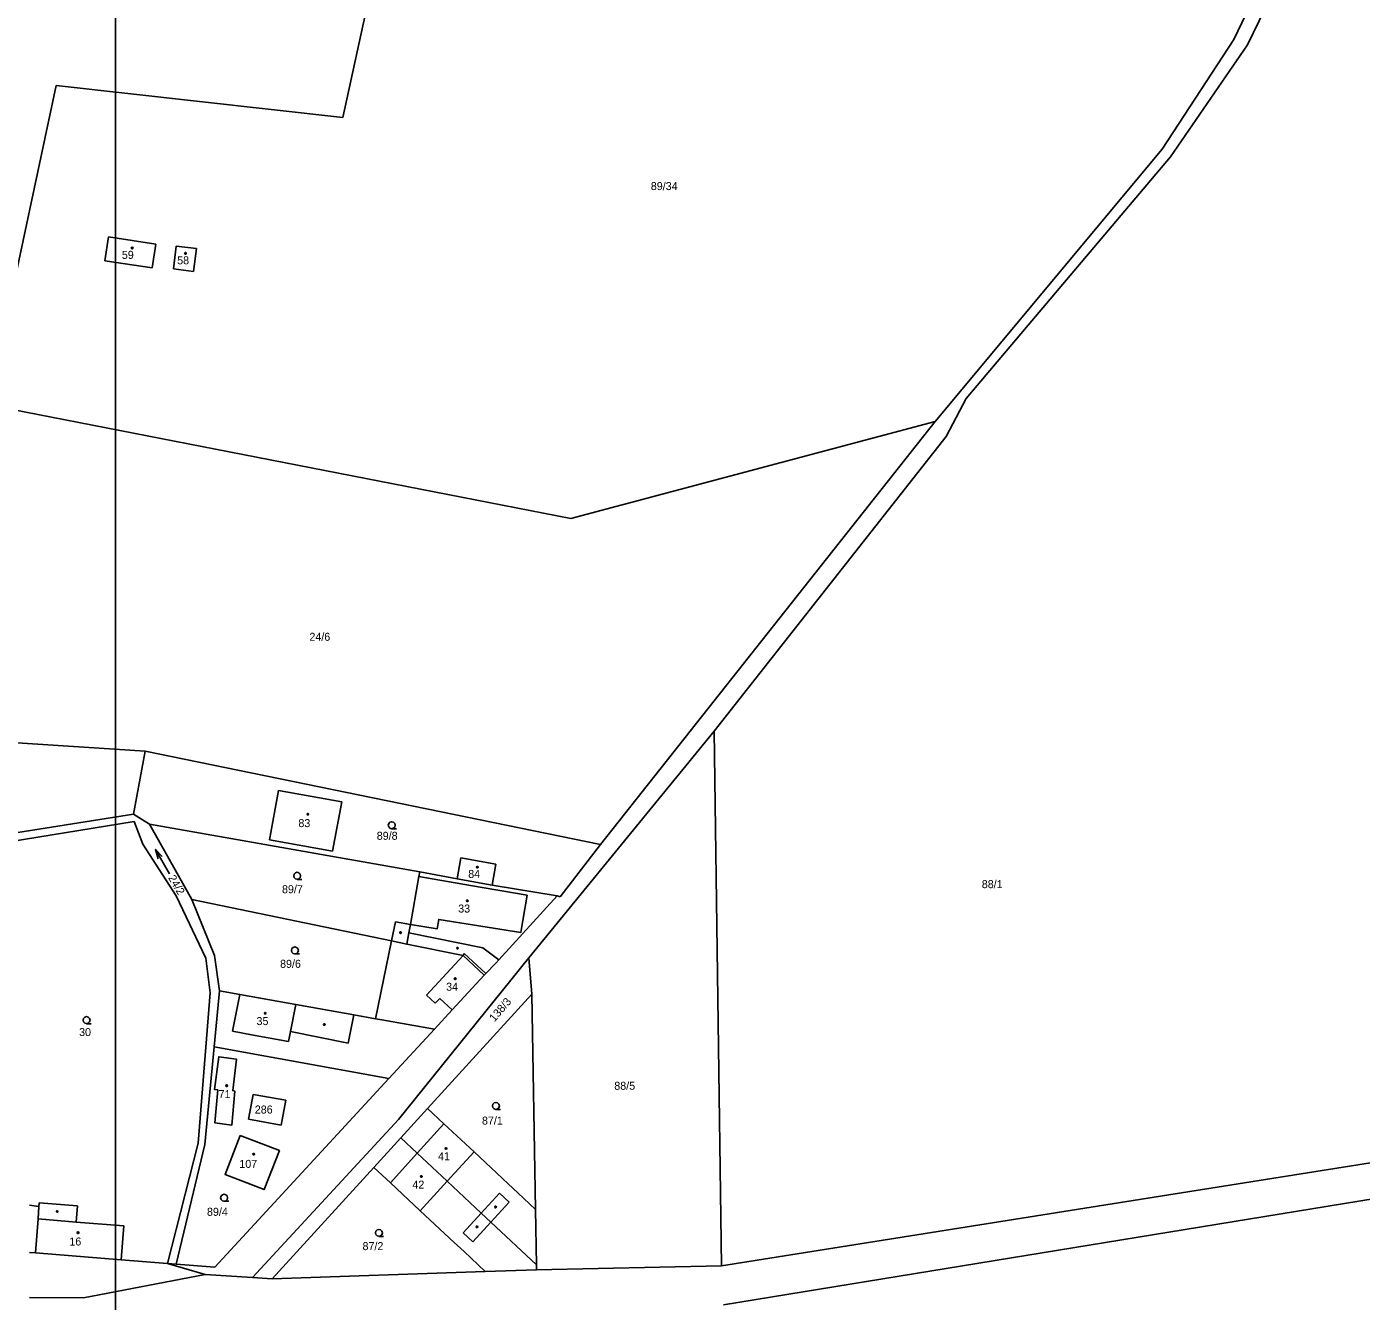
# Model space of a CAD drawing. Extents: x -752343 to -750336, y -1035826 to -1033329.
# Drawn here: x -751372.1 to -751088.6, y -1034441.1 to -1034170.4 of the extents above; entities that cross this region are included whole.
import ezdxf

# ---------------------------------------------------------------- set-up
doc = ezdxf.new("R2010")
doc.units = 0
for name, color, linetype in [('Default', 7, 'Continuous'), ('KN_HRANICE', 7, 'Continuous'), ('KN_KULTURY', 7, 'Continuous'), ('KN_PARCELY', 7, 'Continuous'), ('KN_SLUCKY', 7, 'Continuous'), ('LEGENDA', 7, 'Continuous')]:
    doc.layers.add(name, color=color, linetype=linetype)

# ---------------------------------------------------------------- blocks, each defined once
blk = doc.blocks.new('304')
at = {"layer": 'Default'}
blk.add_lwpolyline([(0, 0), (-0.38, 0.1), (-0.65, 0.37), (-0.75, 0.74), (-0.65, 1.11), (-0.38, 1.38), (-0.01, 1.48), (0.36, 1.38), (0.63, 1.11), (0.73, 0.73), (0.63, 0.35), (0.36, 0.08), (-0.02, -0.02), (0.98, -0.02)], dxfattribs=at)
blk = doc.blocks.new('NAHRADNI_SYMBOL')
at = {"layer": 'Default'}
blk.add_lwpolyline([(0.09, 0.15), (0.18, 0), (0.09, -0.15), (-0.09, -0.15), (-0.18, 0), (-0.09, 0.15), (0.09, 0.15)], dxfattribs=at)
blk = doc.blocks.new('802')
at = {"layer": 'Default'}
blk.add_line((-3, 0), (3, 0), dxfattribs=at)
blk.add_lwpolyline([(1, 0.5), (3, 0), (1, -0.5)], dxfattribs=at)
blk = doc.blocks.new('402')
at = {"layer": 'Default'}
blk.add_lwpolyline([(0.09, 0.15), (0.18, 0), (0.09, -0.15), (-0.09, -0.15), (-0.18, 0), (-0.09, 0.15), (0.09, 0.15)], dxfattribs=at)

msp = doc.modelspace()

# ---------------------------------------------------------------- linework, layer by layer
at = {"layer": 'KN_HRANICE'}
for p, q in [((-751291.67, -1034128.59), (-751304.92, -1034189.73)), ((-751115.71, -1034173.12), (-751109.66, -1034160.4)), ((-751112.8, -1034174.3), (-751106.52, -1034161.33)), ((-751130.94, -1034196.4), (-751115.71, -1034173.12)), ((-751129.14, -1034198.04), (-751112.8, -1034174.3)), ((-751365.81, -1034182.88), (-751380.27, -1034250.73)), ((-751304.92, -1034189.73), (-751365.81, -1034182.88)), ((-751179.17, -1034254.29), (-751130.94, -1034196.4)), ((-751172.58, -1034249.37), (-751129.14, -1034198.04)), ((-751354.68, -1034215.08), (-751355.44, -1034220.15)), ((-751344.64, -1034216.57), (-751354.68, -1034215.08)), ((-751345.39, -1034221.65), (-751344.64, -1034216.57)), ((-751340.3, -1034217), (-751340.9, -1034221.84)), ((-751336.02, -1034217.53), (-751340.3, -1034217)), ((-751336.62, -1034222.38), (-751336.02, -1034217.53)), ((-751355.44, -1034220.15), (-751345.39, -1034221.65)), ((-751340.9, -1034221.84), (-751336.62, -1034222.38)), ((-751176.82, -1034257.44), (-751172.58, -1034249.37)), ((-751256.5, -1034274.89), (-751380.27, -1034250.73)), ((-751179.17, -1034254.29), (-751256.5, -1034274.89)), ((-751250.21, -1034344.11), (-751179.17, -1034254.29)), ((-751176.82, -1034257.44), (-751226.06, -1034320.01)), ((-751226.06, -1034320.01), (-751265.43, -1034368.17)), ((-751226.06, -1034320.01), (-751224.54, -1034433.54)), ((-751401.38, -1034320.74), (-751346.88, -1034324.25)), ((-751346.88, -1034324.25), (-751349.38, -1034337.65)), ((-751250.21, -1034344.11), (-751346.88, -1034324.25)), ((-751318.58, -1034332.59), (-751320.52, -1034343.11)), ((-751305.12, -1034335.02), (-751318.58, -1034332.59)), ((-751307.12, -1034345.5), (-751305.12, -1034335.02)), ((-751388.63, -1034343.88), (-751349.38, -1034337.65)), ((-751349.22, -1034339.19), (-751386, -1034345.21)), ((-751349.38, -1034337.65), (-751345.97, -1034339.77)), ((-751347.37, -1034344.02), (-751349.22, -1034339.19)), ((-751345.97, -1034339.77), (-751336.97, -1034355.77)), ((-751345.97, -1034339.77), (-751288.59, -1034349.93)), ((-751320.52, -1034343.11), (-751307.12, -1034345.5)), ((-751340.29, -1034354.97), (-751347.37, -1034344.02)), ((-751258.79, -1034355.2), (-751250.21, -1034344.11)), ((-751280.62, -1034351.41), (-751279.88, -1034346.92)), ((-751279.88, -1034346.92), (-751272.41, -1034348.25)), ((-751272.41, -1034348.25), (-751273.19, -1034352.72)), ((-751290.57, -1034361.09), (-751288.76, -1034350.86)), ((-751288.76, -1034350.86), (-751288.59, -1034349.93)), ((-751288.59, -1034349.93), (-751280.62, -1034351.41)), ((-751273.19, -1034352.72), (-751280.62, -1034351.41)), ((-751273.19, -1034352.72), (-751259.44, -1034355.02)), ((-751340.29, -1034354.97), (-751334, -1034368.23)), ((-751294.56, -1034364.56), (-751336.97, -1034355.77)), ((-751332.18, -1034367.69), (-751336.97, -1034355.77)), ((-751271.8, -1034368.57), (-751259.44, -1034355.02)), ((-751259.44, -1034355.02), (-751258.79, -1034355.2)), ((-751294.56, -1034364.56), (-751293.72, -1034360.54)), ((-751293.72, -1034360.54), (-751290.57, -1034361.09)), ((-751298.02, -1034381.09), (-751294.56, -1034364.56)), ((-751291.3, -1034365.23), (-751294.56, -1034364.56)), ((-751279.4, -1034367.69), (-751291.3, -1034365.23)), ((-751334, -1034368.23), (-751333.12, -1034375.56)), ((-751331.09, -1034375.2), (-751332.18, -1034367.69)), ((-751265.43, -1034368.17), (-751293.13, -1034402.46)), ((-751279.4, -1034367.69), (-751274.9, -1034371.84)), ((-751272.46, -1034369.29), (-751271.8, -1034368.57)), ((-751264.81, -1034375.86), (-751265.43, -1034368.17)), ((-751274.9, -1034371.84), (-751274.57, -1034371.5)), ((-751274.57, -1034371.5), (-751272.46, -1034369.29)), ((-751274.9, -1034371.84), (-751281.69, -1034379.21)), ((-751333.12, -1034375.56), (-751335.62, -1034407.54)), ((-751332.24, -1034387.06), (-751331.09, -1034375.2)), ((-751326.76, -1034375.97), (-751331.09, -1034375.2)), ((-751314.88, -1034378.09), (-751326.76, -1034375.97)), ((-751264.81, -1034375.86), (-751286.95, -1034400.14)), ((-751264, -1034421.58), (-751264.81, -1034375.86)), ((-751302.59, -1034380.28), (-751314.88, -1034378.09)), ((-751281.69, -1034379.21), (-751285.48, -1034383.32)), ((-751298.02, -1034381.09), (-751302.59, -1034380.28)), ((-751298.02, -1034381.09), (-751296.63, -1034381.34)), ((-751296.63, -1034381.34), (-751285.48, -1034383.32)), ((-751285.48, -1034383.32), (-751295.13, -1034393.79)), ((-751334.25, -1034407.77), (-751332.24, -1034387.06)), ((-751332.24, -1034387.06), (-751295.13, -1034393.79)), ((-751295.13, -1034393.79), (-751332.07, -1034433.84)), ((-751323.98, -1034397.15), (-751324.94, -1034402.42)), ((-751317.05, -1034398.41), (-751323.98, -1034397.15)), ((-751318, -1034403.67), (-751317.05, -1034398.41)), ((-751324.94, -1034402.42), (-751318, -1034403.67)), ((-751293.13, -1034402.46), (-751324.07, -1034436.04)), ((-751286.95, -1034400.14), (-751292.64, -1034406.38)), ((-751283.44, -1034403.42), (-751286.95, -1034400.14)), ((-751277.06, -1034409.37), (-751283.44, -1034403.42)), ((-751342.13, -1034433.05), (-751335.62, -1034407.54)), ((-751334.25, -1034407.77), (-751340.35, -1034433.19)), ((-751292.64, -1034406.38), (-751298.35, -1034412.65)), ((-751289.12, -1034409.67), (-751292.64, -1034406.38)), ((-751224.54, -1034433.54), (-751060.39, -1034407.52)), ((-751282.76, -1034415.62), (-751289.12, -1034409.67)), ((-751269.84, -1034416.12), (-751277.06, -1034409.37)), ((-751298.35, -1034412.65), (-751319.91, -1034436.3)), ((-751294.83, -1034415.94), (-751298.35, -1034412.65)), ((-751294.83, -1034415.94), (-751288.47, -1034421.88)), ((-751275.54, -1034422.36), (-751282.76, -1034415.62)), ((-751267.78, -1034418.04), (-751269.84, -1034416.12)), ((-751060.35, -1034415.09), (-751224.07, -1034441.83)), ((-751264, -1034421.58), (-751267.78, -1034418.04)), ((-751369.45, -1034421), (-751371.43, -1034420.71)), ((-751369.39, -1034420.17), (-751369.45, -1034421)), ((-751361.26, -1034420.82), (-751369.39, -1034420.17)), ((-751361.26, -1034420.82), (-751361.54, -1034424.27)), ((-751281.25, -1034428.62), (-751288.47, -1034421.88)), ((-751273.48, -1034424.28), (-751275.54, -1034422.36)), ((-751263.79, -1034433.33), (-751264, -1034421.58)), ((-751361.54, -1034424.27), (-751351.42, -1034425.08)), ((-751351.42, -1034425.08), (-751352, -1034432.26)), ((-751263.79, -1034433.33), (-751273.48, -1034424.28)), ((-751370.18, -1034430.8), (-751371.43, -1034430.7)), ((-751352, -1034432.26), (-751370.18, -1034430.8)), ((-751279.19, -1034430.54), (-751281.25, -1034428.62)), ((-751274.67, -1034434.76), (-751279.19, -1034430.54)), ((-751342.13, -1034433.05), (-751352, -1034432.26)), ((-751340.35, -1034433.19), (-751342.13, -1034433.05)), ((-751334.17, -1034435.42), (-751342.13, -1034433.05)), ((-751332.07, -1034433.84), (-751340.35, -1034433.19)), ((-751263.77, -1034434.39), (-751263.79, -1034433.33)), ((-751224.54, -1034433.54), (-751263.77, -1034434.39)), ((-751359.96, -1034440.37), (-751334.17, -1034435.42)), ((-751324.07, -1034436.04), (-751334.17, -1034435.42)), ((-751319.91, -1034436.3), (-751324.07, -1034436.04)), ((-751319.91, -1034436.3), (-751274.67, -1034434.76)), ((-751274.67, -1034434.76), (-751263.77, -1034434.39)), ((-751371.43, -1034440.29), (-751359.96, -1034440.37))]:
    msp.add_line(p, q, dxfattribs=at)
for points in [[(-751331.46, -1034396.21), (-751332.16, -1034396.12), (-751331.28, -1034389.18), (-751327.48, -1034389.71), (-751328.31, -1034396.36), (-751327.89, -1034396.45)], [(-751331.46, -1034396.21), (-751332.1, -1034403.22), (-751328.51, -1034403.71), (-751327.89, -1034396.45)]]:
    msp.add_lwpolyline(points, dxfattribs=at)
msp.add_lwpolyline([(-751326.7, -1034405.86), (-751318.4, -1034409.09), (-751321.63, -1034417.37), (-751329.92, -1034414.14)], close=True, dxfattribs=at)
at = {"layer": 'KN_SLUCKY'}
for p, q in [((-751277.83, -1034352.77), (-751288.76, -1034350.86)), ((-751277.83, -1034352.77), (-751265.76, -1034354.88)), ((-751265.76, -1034354.88), (-751266.7, -1034360.25)), ((-751290.88, -1034362.85), (-751291.3, -1034365.23)), ((-751290.57, -1034361.09), (-751290.88, -1034362.85)), ((-751275.21, -1034366), (-751290.88, -1034362.85)), ((-751279.4, -1034367.69), (-751287.14, -1034376.09)), ((-751279.16, -1034367.26), (-751279.4, -1034367.69)), ((-751279.16, -1034367.26), (-751274.57, -1034371.5)), ((-751275.21, -1034366), (-751271.8, -1034368.57)), ((-751326.76, -1034375.97), (-751328.32, -1034383.76)), ((-751287.14, -1034376.09), (-751285.3, -1034377.79)), ((-751285.3, -1034377.79), (-751284.35, -1034376.76)), ((-751284.35, -1034376.76), (-751281.69, -1034379.21)), ((-751316.04, -1034383.82), (-751314.88, -1034378.09)), ((-751302.59, -1034380.28), (-751303.77, -1034386.3)), ((-751324.32, -1034384.5), (-751328.32, -1034383.76)), ((-751316.47, -1034385.94), (-751324.32, -1034384.5)), ((-751316.47, -1034385.94), (-751316.04, -1034383.82)), ((-751303.77, -1034386.3), (-751316.04, -1034383.82)), ((-751289.12, -1034409.67), (-751283.44, -1034403.42)), ((-751294.83, -1034415.94), (-751289.12, -1034409.67)), ((-751282.76, -1034415.62), (-751277.06, -1034409.37)), ((-751288.47, -1034421.88), (-751282.76, -1034415.62)), ((-751275.54, -1034422.36), (-751271.68, -1034418.13)), ((-751269.62, -1034420.05), (-751271.68, -1034418.13)), ((-751369.45, -1034421), (-751369.65, -1034423.62)), ((-751279.35, -1034426.54), (-751275.54, -1034422.36)), ((-751273.48, -1034424.28), (-751269.62, -1034420.05)), ((-751369.65, -1034423.62), (-751370.18, -1034430.8)), ((-751369.65, -1034423.62), (-751361.54, -1034424.27)), ((-751277.29, -1034428.46), (-751273.48, -1034424.28)), ((-751277.29, -1034428.46), (-751279.35, -1034426.54))]:
    msp.add_line(p, q, dxfattribs=at)
msp.add_lwpolyline([(-751266.7, -1034360.25), (-751267.14, -1034362.78), (-751284.54, -1034359.99), (-751284.86, -1034362), (-751290.57, -1034361.09)], dxfattribs=at)
at = {"layer": 'LEGENDA'}
msp.add_lwpolyline([(-751353.18, -1034559.75), (-751947.18, -1034559.75), (-751947.18, -1034139.75), (-751353.18, -1034139.75)], close=True, dxfattribs=at)

# ---------------------------------------------------------------- block references
at = {"layer": 'KN_KULTURY'}
for name, p in [('NAHRADNI_SYMBOL', (-751349.66, -1034217.42)), ('402', (-751338.34, -1034218.55)), ('402', (-751312.36, -1034337.67)), ('304', (-751294.54, -1034340.73)), ('402', (-751276.35, -1034348.89)), ('304', (-751314.61, -1034351.47)), ('402', (-751278.5, -1034356.05)), ('402', (-751292.68, -1034362.82)), ('304', (-751315.1, -1034367.31)), ('402', (-751280.57, -1034366.08)), ('402', (-751281.07, -1034372.58)), ('402', (-751321.42, -1034379.92)), ('304', (-751359.34, -1034382.12)), ('402', (-751308.86, -1034382.34)), ('402', (-751329.6, -1034395.31)), ('304', (-751272.41, -1034400.34)), ('402', (-751323.86, -1034409.84)), ('402', (-751283.01, -1034408.65)), ('402', (-751288.24, -1034414.58)), ('304', (-751330.13, -1034419.84)), ('402', (-751365.59, -1034422.01)), ('402', (-751272.5, -1034421.08)), ('402', (-751276.45, -1034425.28)), ('402', (-751361.15, -1034426.52)), ('304', (-751297.25, -1034427.3))]:
    msp.add_blockref(name, p, dxfattribs=at)
at = {"layer": 'KN_KULTURY', "rotation": 119.805475}
msp.add_blockref('802', (-751343.23, -1034347.73), dxfattribs=at)

# ---------------------------------------------------------------- texts
at = {"layer": 'KN_PARCELY'}
for s, p in [('89/34', (-751239.52, -1034205.12)), ('59', (-751351.85, -1034219.72)), ('58', (-751340.1, -1034220.88)), ('24/6', (-751312.02, -1034300.83)), ('83', (-751314.36, -1034340.4)), ('89/8', (-751297.72, -1034343.09)), ('84', (-751278.3, -1034351.19)), ('88/1', (-751169.24, -1034353.36)), ('89/7', (-751317.84, -1034354.44)), ('33', (-751280.42, -1034358.54)), ('89/6', (-751318.25, -1034370.28)), ('34', (-751282.99, -1034375.15)), ('35', (-751323.25, -1034382.44)), ('30', (-751360.93, -1034384.77)), ('71', (-751331.31, -1034397.96)), ('88/5', (-751247.28, -1034396.18)), ('286', (-751323.62, -1034401.22)), ('87/1', (-751275.38, -1034403.57)), ('107', (-751326.9, -1034412.76)), ('41', (-751284.69, -1034411.13)), ('42', (-751290.15, -1034417.17)), ('89/4', (-751333.77, -1034422.94)), ('16', (-751362.99, -1034429.25)), ('87/2', (-751300.74, -1034430.23))]:
    msp.add_text(s, height=1.7, dxfattribs=at).set_placement(p)
for s, rotation, p in [('24/2', 300.23, (-751342.07, -1034351.16)), ('138/3', 49.332, (-751272.72, -1034381.85))]:
    msp.add_text(s, height=1.7, rotation=rotation, dxfattribs=at).set_placement(p)

doc.saveas('drawing.dxf')
